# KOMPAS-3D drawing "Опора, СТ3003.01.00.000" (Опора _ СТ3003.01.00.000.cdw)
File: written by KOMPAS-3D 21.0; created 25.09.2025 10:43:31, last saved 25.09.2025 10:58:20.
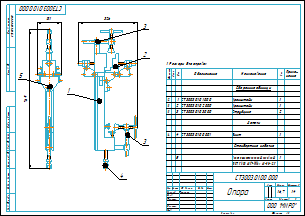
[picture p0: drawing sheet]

Sheet 1: A3, landscape

Document properties: Полное имя файла: C:\Users\1\Yandex.Disk\Документы\Новая папка\Стапель №2\Стапель _ СТ3003.00.00.000\Опора _ СТ3003.01.00.000\2D\Опора _ СТ3003.01.00.000.cdw; Масса: 16.700346

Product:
- Part/product: Опора  | designation СТ3003.01.00.000
    Масса: 16.700346
    Форматы листов документа: A3
  - Component [detail]: Винт  | designation СТ3003.01.00.001  | pos. 4  | Материал: Круг$d30 ГОСТ 2590-2006;Ст3сп ГОСТ 535-2005$ (density 7850 kg/m3); Масса: 0.303608; Форматы листов документа: A4; additional columns: 120; source file: ..\3D\Винт _ СТ3003.01.00.001.m3d, Винт _ СТ3003.01.00.001.cdw
  - Component [standard]: Винт с шестигранной головкой ГОСТ Р ИСО 4017-М16 x 45-5.8-A2P  | pos. 5  | Материал: Сталь (density 1000 kg/m3); Масса: 0.01392; Раздел спецификации: Стандартные изделия; Рассекать на разрезах: no; additional columns: ГОСТ Р ИСО 4017-2013; М16 x 45 - 5.8 - A2P
  - Component [assembly]: Струбцина  | designation СТ3003.01.03.000-01  | pos. 3  | Масса: 1.075052; Раздел спецификации: Сборочные единицы; Форматы листов документа: A3; source file: ..\3D\Струбцина _ СТ3003.01.03.000\Струбцина _ СТ3003.01.03.000.a3d, Струбцина _ СТ3003.01.03.000\Струбцина _ СТ3003.01.03.000.cdw
  - Component [assembly]: Струбцина  | designation СТ3003.01.03.000  | pos. 3  | Масса: 1.103282; Раздел спецификации: Сборочные единицы; Форматы листов документа: A3; source file: ..\3D\Струбцина _ СТ3003.01.03.000\Струбцина _ СТ3003.01.03.000.a3d, Струбцина _ СТ3003.01.03.000\Струбцина _ СТ3003.01.03.000.cdw
  - Component [assembly]: Кронштейн  | designation СТ3003.01.02.000  | pos. 2  | Масса: 4.787723; Форматы листов документа: A3; source file: ..\3D\Кронштейн _ СТ3003.01.02.000\Кронштейн _ СТ3003.01.02.000.a3d, Кронштейн _ СТ3003.01.02.000\Кронштейн _ СТ3003.01.02.000.cdw
  - Component [assembly]: Кронштейн  | designation СТ3003.01.01.000  | pos. 1  | Масса: 9.381703; Форматы листов документа: A2; source file: ..\3D\Кронштейн _ СТ3003.01.01.000\Кронштейн _ СТ3003.01.01.000.a3d, Кронштейн _ СТ3003.01.01.000\Кронштейн _ СТ3003.01.01.000.cdw

Title block, sheet 1: Наименование: Опора; designation: СТ3003.01.00.000; Масса: 16,7; Количество листов документа: 1; organisation: ООО "МИРО"; Форматы листов документа: A3; stored path: C:\Users\1\Yandex.Disk\Документы\Новая папка\Стапель №2\Стапель _ СТ3003.00.00.000\Опора _ СТ3003.01.00.000\3D\Опора _ СТ3003.01.00.000.cdw; Разработал: Тимонин

Referenced files in C:\Users\1\Yandex.Disk\Документы\Новая папка\Стапель №2\Стапель _ СТ3003.00.00.000\Опора _ СТ3003.01.00.000\3D\Кронштейн _ СТ3003.01.01.000\: Кронштейн _ СТ3003.01.01.000.a3d, Планка _ СТ3003.01.01.005.m3d, Направляющая _ СТ3003.01.01.003.m3d, Пластина _ СТ3003.01.01.006.m3d, Косынка _ СТ3003.01.01.002.m3d, Упор _ СТ.3003.01.01.007.m3d, Винт _ СТ3003.01.01.001.m3d, Опора _ СТ3003.01.01.004.m3d
Referenced files in C:\Users\1\Yandex.Disk\Документы\Новая папка\Стапель №2\Стапель _ СТ3003.00.00.000\Опора _ СТ3003.01.00.000\2D\Кронштейн _ СТ3003.01.01.000\: Кронштейн _ СТ3003.01.01.000.cdw
Referenced files in C:\Users\1\Yandex.Disk\Документы\Новая папка\Стапель №2\Стапель _ СТ3003.00.00.000\Опора _ СТ3003.01.00.000\3D\: Винт _ СТ3003.01.00.001.m3d, Опора _ СТ3003.01.00.000.a3d
Referenced files in C:\Users\1\Yandex.Disk\Документы\Новая папка\Стапель №2\Стапель _ СТ3003.00.00.000\Опора _ СТ3003.01.00.000\2D\: Винт _ СТ3003.01.00.001.cdw
Referenced files in C:\Users\1\Yandex.Disk\Документы\Новая папка\Стапель №2\Стапель _ СТ3003.00.00.000\Опора _ СТ3003.01.00.000\3D\Струбцина _ СТ3003.01.03.000\: Струбцина _ СТ3003.01.03.000.a3d, Опора _ СТ3003.01.03.001.m3d, Ось _ СТ3003.01.03.002.m3d
Referenced files in C:\Users\1\Yandex.Disk\Документы\Новая папка\Стапель №2\Стапель _ СТ3003.00.00.000\Опора _ СТ3003.01.00.000\2D\Струбцина _ СТ3003.01.03.000\: Струбцина _ СТ3003.01.03.000.cdw
Referenced files in C:\Users\1\Yandex.Disk\Документы\Новая папка\Стапель №2\Стапель _ СТ3003.00.00.000\Опора _ СТ3003.01.00.000\3D\Кронштейн _ СТ3003.01.02.000\: Кронштейн _ СТ3003.01.02.000.a3d, Пластина _ СТ3003.01.02.002.m3d, Направляющая _ СТ3003.01.02.001.m3d, Упор _ СТ3003.01.02.003.m3d
Referenced files in C:\Users\1\Yandex.Disk\Документы\Новая папка\Стапель №2\Стапель _ СТ3003.00.00.000\Опора _ СТ3003.01.00.000\2D\Кронштейн _ СТ3003.01.02.000\: Кронштейн _ СТ3003.01.02.000.cdw
Referenced files in C:\Users\1\Yandex.Disk\Документы\Новая папка\Стапель №2\Стапель _ СТ3003.00.00.000\Опора _ СТ3003.01.00.000\3D\Кронштейн _ СТ3003.01.01.000\Основание _ СТ3003.01.01.100\: Пластина _ СТ3003.01.01.101.m3d, Пластина _ СТ3003.01.01.102.m3d, Основание _ СТ3003.01.01.100.a3d
Referenced files in C:\Program Files\ASCON\KOMPAS-3D v21\Libs\PartLib\DATA\VAULT\Methods\Kompas\3D\: PLib_Screw_GOST_11738_1500.m3d, PLib_Washer_1_712.m3d, PLib_Piata_GOST_13437-68_813.m3d, PLib_Pin_3128_712.m3d, PLib_Bolt_1_900.m3d
Referenced files in C:\Program Files\ASCON\KOMPAS-3D v21\Libs\PARTLib\DATA\vault\Methods\Kompas\3D\: PLib_Nut_ISO_1100.m3d, PLib_Bolt_1_ISO_1100.m3d
Referenced files in C:\Program Files\ASCON\KOMPAS-3D v21\Libs\PARTLib\DATA\vault\Methods\Kompas\3D\Holding_devices\13447_13430_13431_13426_8921\: PLib_Pin_GOST_3128-70_813.m3d, Plib_Screw_GOST_13433_13435_813.m3d, Plib_Screw_GOST_13431-68_813.a3d
Referenced files: PLib_Hand_lever_GOST_13447-68_813.a3d
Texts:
  СТ3003.01.01.000
  Кронштейн
  СТ3003.01.00.001
  Винт
  Винт с шестигранной головкой ГОСТ Р ИСО 4017-М16 x 45-5.8-A2P
  Винт с шестигранной головкой
  ГОСТ Р ИСО
  СТ3003.01.03.000 - 01
  СТ3003.01.03.000 - 01
  Струбцина
  СТ3003.01.03.000-01
  СТ3003.01.03.000
  СТ3003.01.02.000
  ГОСТ Р ИСО 4017-М16 x 45-5.8-A2P
  СТ3003.00.00.000
  Пластина
  СТ3003.01.01.101
  СТ3003.01.01.101 Пластина
  СТ3003.01.01.102
  СТ3003.01.01.102 Пластина
  Основание
  СТ3003.01.01.100
  СТ3003.01.01.100 Основание
  Планка
  СТ3003.01.01.005
  СТ3003.01.01.005 Планка
  Направляющая
  СТ3003.01.01.003
  СТ3003.01.01.003 Направляющая
  СТ3003.01.01.006
  СТ3003.01.01.006 Пластина
  Косынка
  СТ3003.01.01.002
  СТ3003.01.01.002 Косынка
  Упор
  СТ3003.01.01.007
  СТ3003.01.01.007 Упор
  СТ3003.01.01.001
  СТ3003.01.01.001 Винт
  Винт М8-6gx25.56.019 ГОСТ 11738-84
  Шайба A.8.01.10.019 ГОСТ 11371-78
  Винт М6-6gx20.56.019 ГОСТ 11738-84
  СТ3003.01.01.004
  СТ3003.01.01.004 Опора
  Гайка шестигранная низкая ГОСТ ISO 4035-М12-05-A2P
  СТ3003.01.01.000 Кронштейн
  СТ3003.01.02.002
  СТ3003.01.02.002 Пластина
  СТ3003.01.02.001
  СТ3003.01.02.001 Направляющая
  СТ3003.01.02.003
  СТ3003.01.02.003 Упор
  Винт М8-6gx35.56.019 ГОСТ 11738-84
  СТ3003.01.02.000 Кронштейн
  СТ3003.01.03.001
  СТ3003.01.03.001 Опора
  Ось
  СТ3003.01.03.002
  СТ3003.01.03.002 Ось
  ГОСТ 3128-70 Штифты цилиндрические
  ГОСТ 13429-68 Винты нажимные с концом под пяту
  Винт 7006-0537 ГОСТ 13431-68
  Пята 7007-0035 ГОСТ 13437-68
  Штифт 4x16 ГОСТ 3128-70
  Шайба A 6.01.10.019 ГОСТ 6958-78
  Винт с шестигранной головкой ГОСТ Р ИСО 4017-М6 x 25-5.8-A2P
  СТ3003.01.03.000 Струбцина
  Болт М6-6gx25.58.019 ГОСТ 7798-70
  СТ3003.01.03.000-01 Струбцина
  СТ3003.01.00.001 Винт
  СТ3003.01.00.000 Опора
Dimensions and other numbers on the sheet: 1; 5.8; 2; 4; 5; 3; 1:4; 16,7; 01

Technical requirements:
  Размеры для справок.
